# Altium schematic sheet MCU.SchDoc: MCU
size A3; DocumentNumber: 4; SheetNumber: 4; SheetTotal: 6
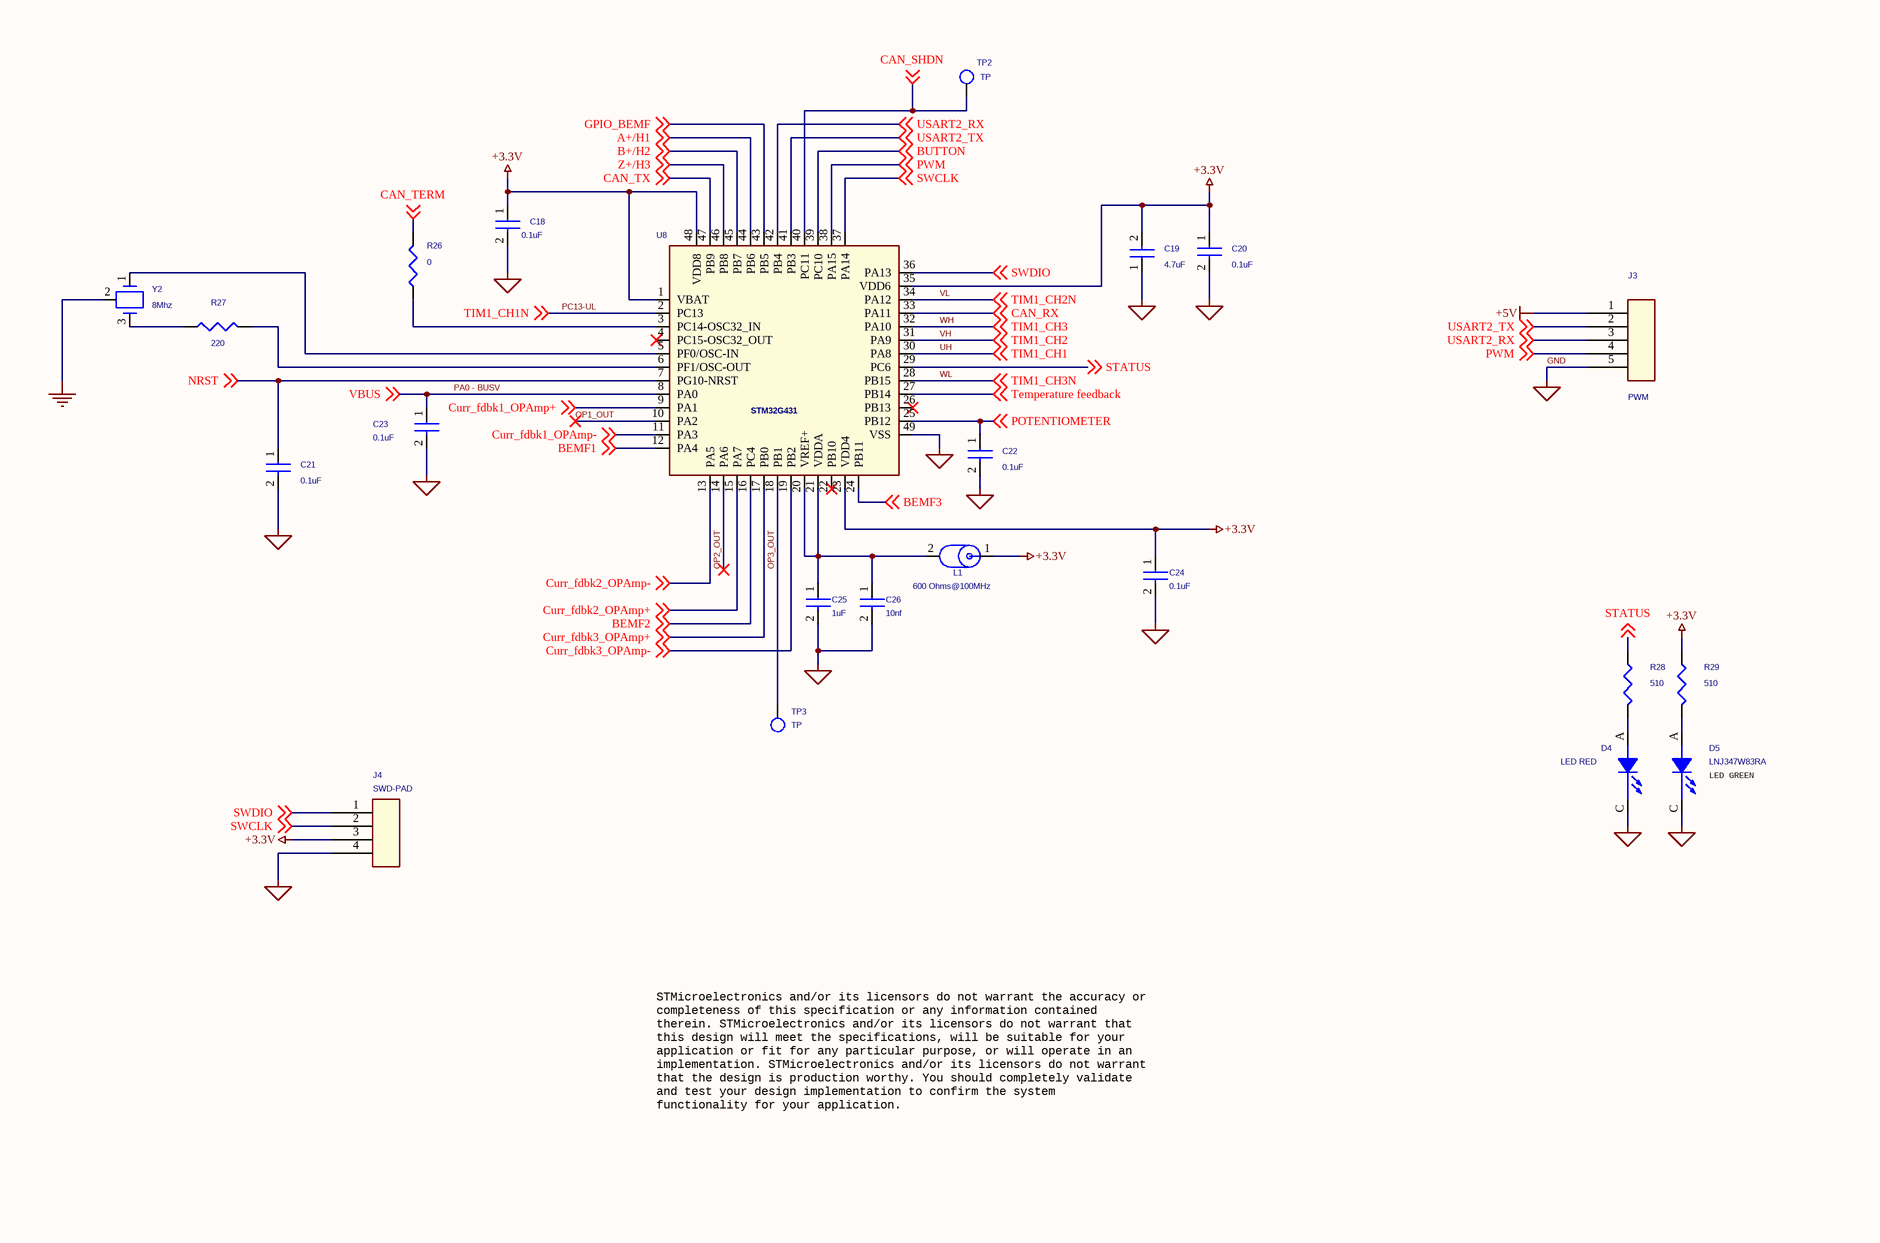
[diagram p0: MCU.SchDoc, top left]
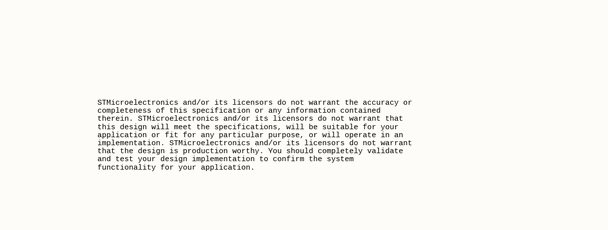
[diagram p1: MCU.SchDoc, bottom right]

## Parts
C18  0.1uF  [C_0402]
C19  4.7uF  [C_0603]
C20  0.1uF  [C_0402]
C21  0.1uF  [C_0402]
C22  0.1uF  [C_0402]
C23  0.1uF  [C_0402]
C24  0.1uF  [C_0402]
C25  1uF  [C_0402]
C26  10nf  [C_0402]
D4  LED RED  [D_0402_Led_red]
D5  LNJ347W83RA  [D_0402_Led_green]
J3  PWM  [SOLDER_PAD_5PIN_SMD]
J4  SWD-PAD  [SOLDER_PAD_4PIN_rect_SMD]
L1  600 Ohms@100MHz  [L_0402]
R26  0  [R_0402]
R27  220  [R_0402]
R28  510  [R_0402]
R29  510  [R_0402]
TP2  TP  [test_point_100_smd]
TP3  TP  [test_point_100_smd]
U8  STM32G431  [qfn49p50_700x700x60l40x25t560n]
Y2  8Mhz  [murata_cstce8m00g15c99-r0]

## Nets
+3.3V: C18.1 C19.2 C20.1 C24.1 J4.3 L1.1 R29.1 U8.1(VBAT) U8.23(VDD4) U8.35(VDD6) U8.48(VDD8)
+5V: J3.1
GND: C18.2 C19.1 C20.2 C21.2 C22.2 C23.2 C24.2 C25.2 C26.2 D4.C(CATHODE) D5.C(CATHODE) J3.5 J4.4 U8.49(VSS) Y2.2  [also labelled GND_SIGNAL]
A+/H1: U8.44(PB6) ; off-sheet A+/H1
B+/H2: U8.45(PB7) ; off-sheet B+/H2
BEMF1: U8.12(PA4) ; off-sheet BEMF1
BEMF2: U8.16(PC4) ; off-sheet BEMF2
BEMF3: U8.24(PB11) ; off-sheet BEMF3
BUTTON: U8.39(PC10) ; off-sheet BUTTON
CAN_RX: U8.33(PA11) ; off-sheet CAN_RX
CAN_SHDN: TP2.1 U8.40(PC11) ; off-sheet CAN_SHDN
CAN_TERM: R26.2 ; off-sheet CAN_TERM
CAN_TX: U8.47(PB9) ; off-sheet CAN_TX
Curr_fdbk1_OPAmp+: U8.9(PA1) ; off-sheet Curr_fdbk1_OPAmp+
Curr_fdbk1_OPAmp-: U8.11(PA3) ; off-sheet Curr_fdbk1_OPAmp-
Curr_fdbk2_OPAmp+: U8.15(PA7) ; off-sheet Curr_fdbk2_OPAmp+
Curr_fdbk2_OPAmp-: U8.13(PA5) ; off-sheet Curr_fdbk2_OPAmp-
Curr_fdbk3_OPAmp+: U8.17(PB0) ; off-sheet Curr_fdbk3_OPAmp+
Curr_fdbk3_OPAmp-: U8.19(PB2) ; off-sheet Curr_fdbk3_OPAmp-
GPIO_BEMF: U8.43(PB5) ; off-sheet GPIO_BEMF
NRST: C21.1 U8.7(PG10-NRST) ; off-sheet NRST
OP1_OUT: U8.10(PA2)
OP2_OUT: U8.14(PA6)
OP3_OUT: TP3.1 U8.18(PB1)
PA0 - BUSV: C23.1 U8.8(PA0) ; off-sheet VBUS  [also labelled VBUS]
PC13-UL: U8.2(PC13) ; off-sheet TIM1_CH1N  [also labelled TIM1_CH1N]
POTENTIOMETER: C22.1 U8.25(PB12) ; off-sheet POTENTIOMETER
PWM: J3.4 U8.38(PA15) ; off-sheet PWM
STATUS: R28.1 U8.29(PC6) ; off-sheet STATUS
SWCLK: J4.2 U8.37(PA14) ; off-sheet SWCLK
SWDIO: J4.1 U8.36(PA13) ; off-sheet SWDIO
Temperature feedback: U8.27(PB14) ; off-sheet Temperature feedback
UH: U8.30(PA8) ; off-sheet TIM1_CH1  [also labelled TIM1_CH1]
USART2_RX: J3.3 U8.42(PB4) ; off-sheet USART2_RX
USART2_TX: J3.2 U8.41(PB3) ; off-sheet USART2_TX
VH: U8.31(PA9) ; off-sheet TIM1_CH2  [also labelled TIM1_CH2]
VL: U8.34(PA12) ; off-sheet TIM1_CH2N  [also labelled TIM1_CH2N]
WH: U8.32(PA10) ; off-sheet TIM1_CH3  [also labelled TIM1_CH3]
WL: U8.28(PB15) ; off-sheet TIM1_CH3N  [also labelled TIM1_CH3N]
Z+/H3: U8.46(PB8) ; off-sheet Z+/H3
NetC25_1: C25.1 C26.1 L1.2 U8.20(VREF+) U8.21(VDDA)
NetD4_A: D4.A(ANODE) R28.2
NetD5_A: D5.A(ANODE) R29.2
NetR26_1: R26.1 U8.3(PC14-OSC32_IN)
NetR27_1: R27.1 Y2.3
NetR27_2: R27.2 U8.6(PF1/OSC-OUT)
NetU8_5: U8.5(PF0/OSC-IN) Y2.1

Not connected (* = marked no-connect by the designer): U8 4(PC15-OSC32_OUT)* 22(PB10)* 26(PB13)*

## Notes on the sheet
- (near D5) LED GREEN
- STMicroelectronics and/or its licensors do not warrant the accuracy or
  completeness of this specification or any information contained
  therein. STMicroelectronics and/or its licensors do not warrant that
  this design will meet the specifications, will be suitable for your
  application or fit for any particular purpose, or will operate in an
  implementation. STMicroelectronics and/or its licensors do not warrant
  that the design is production worthy. You should completely validate
  and test your design implementation to confirm the system
  functionality for your application.

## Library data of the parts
C18 C22 = CAP_Dup1: CAP CER 0.1UF 16V X7R 0402; PART_NUMBER: CAP-00000053; Manufacturer: Wurth Electronics Inc.; Manufacturer PN: 885012205037; Dielectric Type: Capacitors; Tolerance: 10%; CLASS: DISCRETE
C19 = CAP_Dup1: CAP CER 4.7UF 10V X5R 0603; Manufacturer PN: 885012106012; Manufacturer: Wurth Electronics Inc.; PART_NUMBER: TMP-414; CLASS: DISCRETE; Tolerance: 20%; Dielectric Type: Capacitors
C20 C21 C23 C24 = CAP_Dup1: CAP CER 0.1UF 16V X7R 0402; Manufacturer PN: 885012205037; Manufacturer: Wurth Electronics Inc.; PART_NUMBER: CAP-00000053; CLASS: DISCRETE; Tolerance: 10%; Dielectric Type: Capacitors
C25 = CAP_Dup1: CAP CER 1UF 25V X5R 0402; PART_NUMBER: CAP-00000006; Manufacturer: Murata Electronics North America; Manufacturer PN: GRM155R61E105KA12D; Dielectric Type: Capacitors; Tolerance: 10%; CLASS: DISCRETE
C26 = CAP_Dup1: CAP CER 10000PF 16V X7R 0402; PART_NUMBER: TMP-422; Manufacturer: Wurth Electronics Inc.; Manufacturer PN: 885012205031; Dielectric Type: Capacitors; Tolerance: 10%; CLASS: DISCRETE
D4 = LED: DIO, Rectangle with Flat Top, 1.00mm x 0.50mm, VLMS1500-GS08, 20mA, --, --, 0402 (1005 Metric); PART_NUMBER: DIO-00000003; Manufacturer: Vishay Semiconductor Opto Division; CLASS: DISCRETE
D5 = LED: LED GREEN 0402 SMD; PART_NUMBER: TMP-187; Manufacturer: Everlight Electronics; Manufacturer PN: 16-213SYGC/S530-E3/TR8; CLASS: DISCRETE
J3 = CON5: SOLDER PADS
J4 = CON4: SOLDER PADS
L1 = IND_FB: FERRITE BEAD 600 OHM 0402 1LN; Manufacturer PN: BLM15BX601SN1D; Manufacturer: Murata Electronics North America; PART_NUMBER: TMP-492; CLASS: DISCRETE
R26 = RES: RES SMD 0 OHM JUMPER 1/16W 0402; PART_NUMBER: RES-00000073; Manufacturer: Vishay Dale; Manufacturer PN: CRCW04020000Z0ED; Rated Power: 0.063W, 1/16W; CLASS: DISCRETE
R27 = RES: RES SMD 220 OHM 1% 1/16W 0402; PART_NUMBER: TMP-437; Manufacturer: Yageo; Manufacturer PN: RC0402FR-07220RL; Temperature Coefficient: 100ppm/C; Rated Power: 0.063W, 1/16W; CLASS: DISCRETE
R28 R29 = RES: RES SMD 510 OHM 1% 1/16W 0402; PART_NUMBER: TMP-438; Manufacturer: Yageo; Manufacturer PN: RC0402FR-07510RL; Temperature Coefficient: 100ppm/C; Rated Power: 0.063W, 1/16W; CLASS: DISCRETE
TP2 TP3 = TESTPOINT: TEST POINT 1MM  SMD PADSTASCK; PART_NUMBER: TMP-386; CLASS: IO
U8 = STM32_LQFP64_6
Y2 = resonator: CER RES 8.0000MHZ 33PF SMD; Manufacturer PN: CSTNE8M00GH5C000R0; Manufacturer: Murata Electronics North America; PART_NUMBER: TMP-382; CLASS: DISCRETE; Frequency Tolerance: 0.1%; Frequency Stability: 0.13%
